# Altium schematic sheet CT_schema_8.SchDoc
size 226 x 144 mm
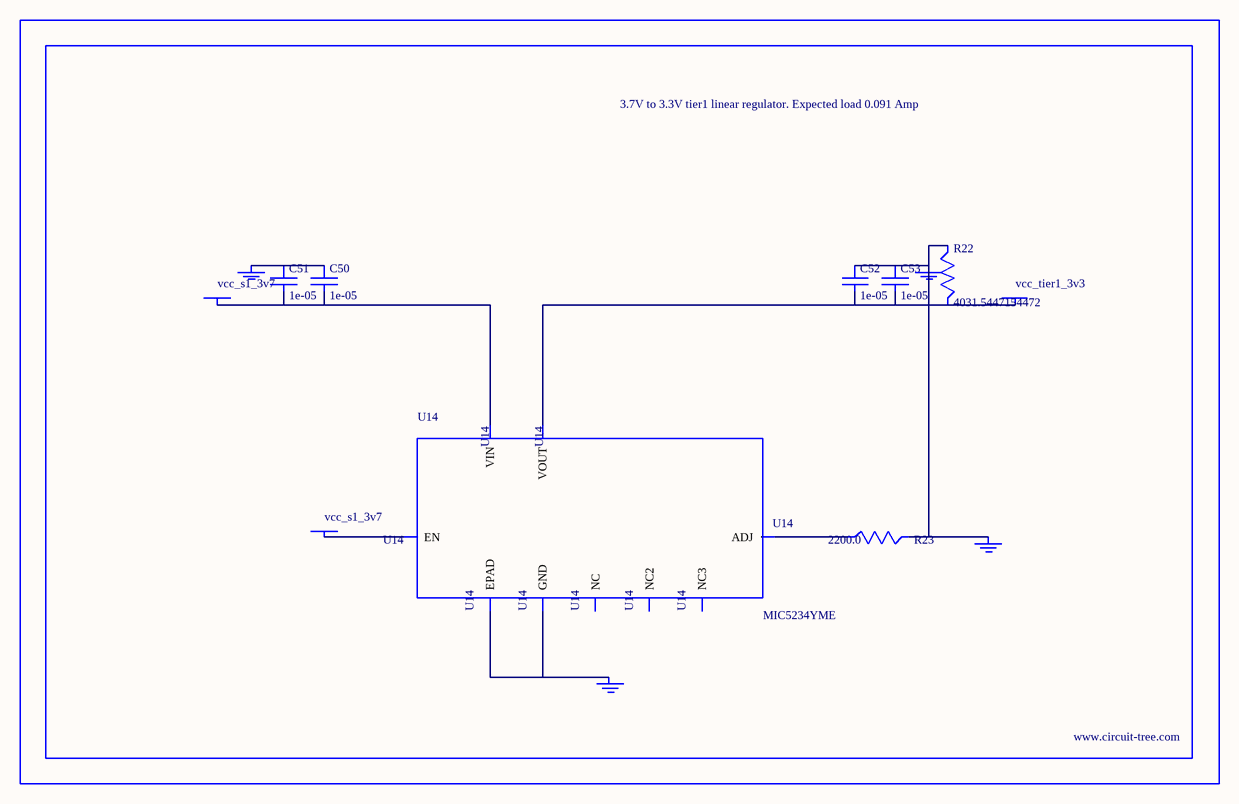
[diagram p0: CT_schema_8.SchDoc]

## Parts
BORDER7  (no value)
C50  1e-05  [C1210]
C51  1e-05  [C1210]
C52  1e-05  [C1210]
C53  1e-05  [C1210]
GND_INSTANCE_7_0  (no value)
GND_INSTANCE_7_1  (no value)
GND_INSTANCE_7_2  (no value)
GND_INSTANCE_7_3  (no value)
POWER_INSTANCE_7_0  vcc_tier1_3v3
POWER_INSTANCE_7_1  vcc_s1_3v7
POWER_INSTANCE_7_2  vcc_s1_3v7
R22  4031.5447154472  [R0603]
R23  2200.0  [R0603]
U14  MIC5234YME  [SOIC-8_EP]

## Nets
NetC50_1: C50.1 C51.1 GND_INSTANCE_7_3.0(GND)
NetC50_2: C50.2 C51.2 POWER_INSTANCE_7_2.0(PWR) U14.8(VIN)
NetC52_1: C52.1 C53.1 GND_INSTANCE_7_0.0(GND) GND_INSTANCE_7_1.0(GND) R22.1 R23.2
NetC52_2: C52.2 C53.2 POWER_INSTANCE_7_0.0(PWR) R22.2 U14.1(VOUT)
NetGND_INSTANCE_7_2_0: GND_INSTANCE_7_2.0(GND) U14.7(GND) U14.EPAD
NetPOWER_INSTANCE_7_1_0: POWER_INSTANCE_7_1.0(PWR) U14.5(EN)
NetR23_1: R23.1 U14.4(ADJ)

Not connected (* = marked no-connect by the designer): U14 2(NC) 3(NC2) 6(NC3)

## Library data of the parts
BORDER7 = BORDER_PAGE7
C50-C53 = C1210C106K5PACTU
GND_INSTANCE_7_0-GND_INSTANCE_7_3 = GND
POWER_INSTANCE_7_0-POWER_INSTANCE_7_2 = PWR
R22 = R22
R23 = RC0603JR-072K2L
